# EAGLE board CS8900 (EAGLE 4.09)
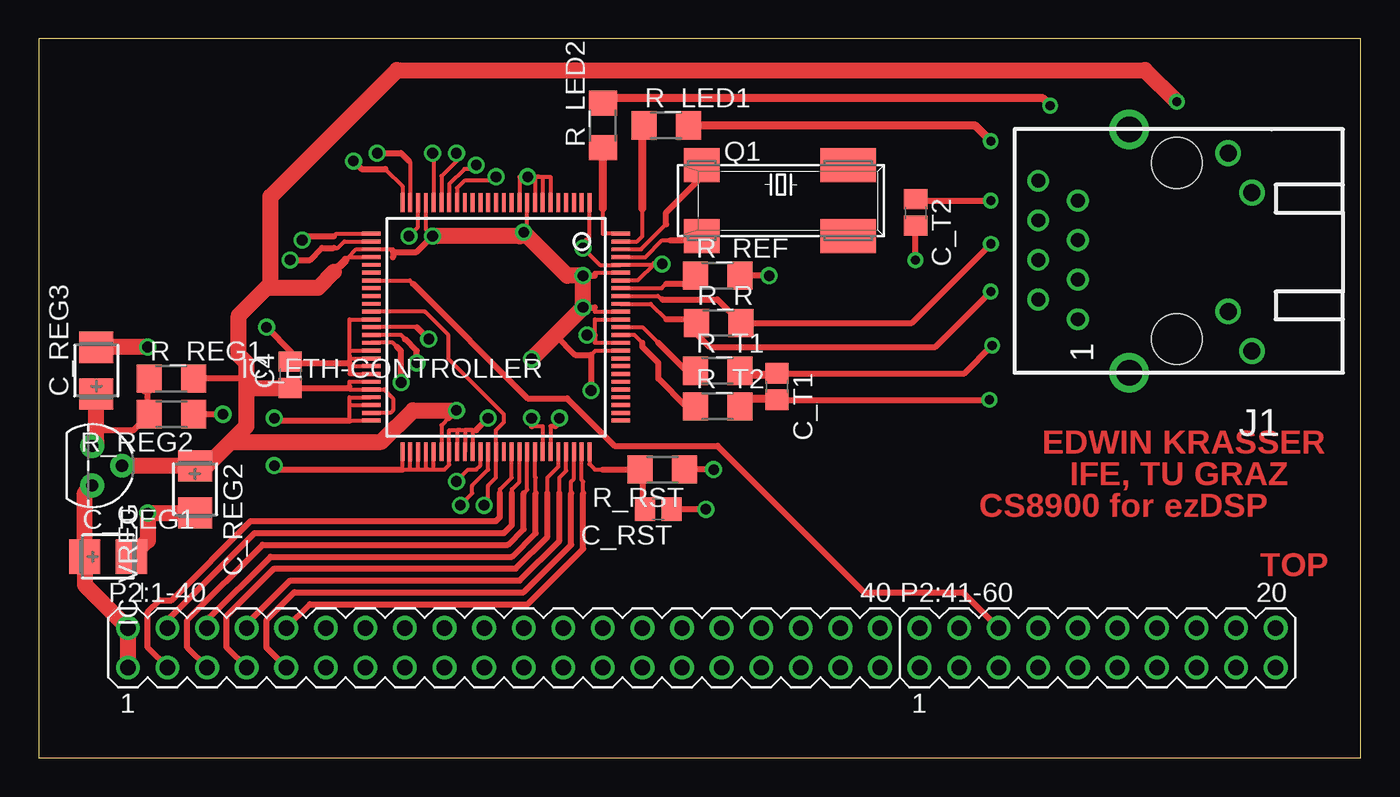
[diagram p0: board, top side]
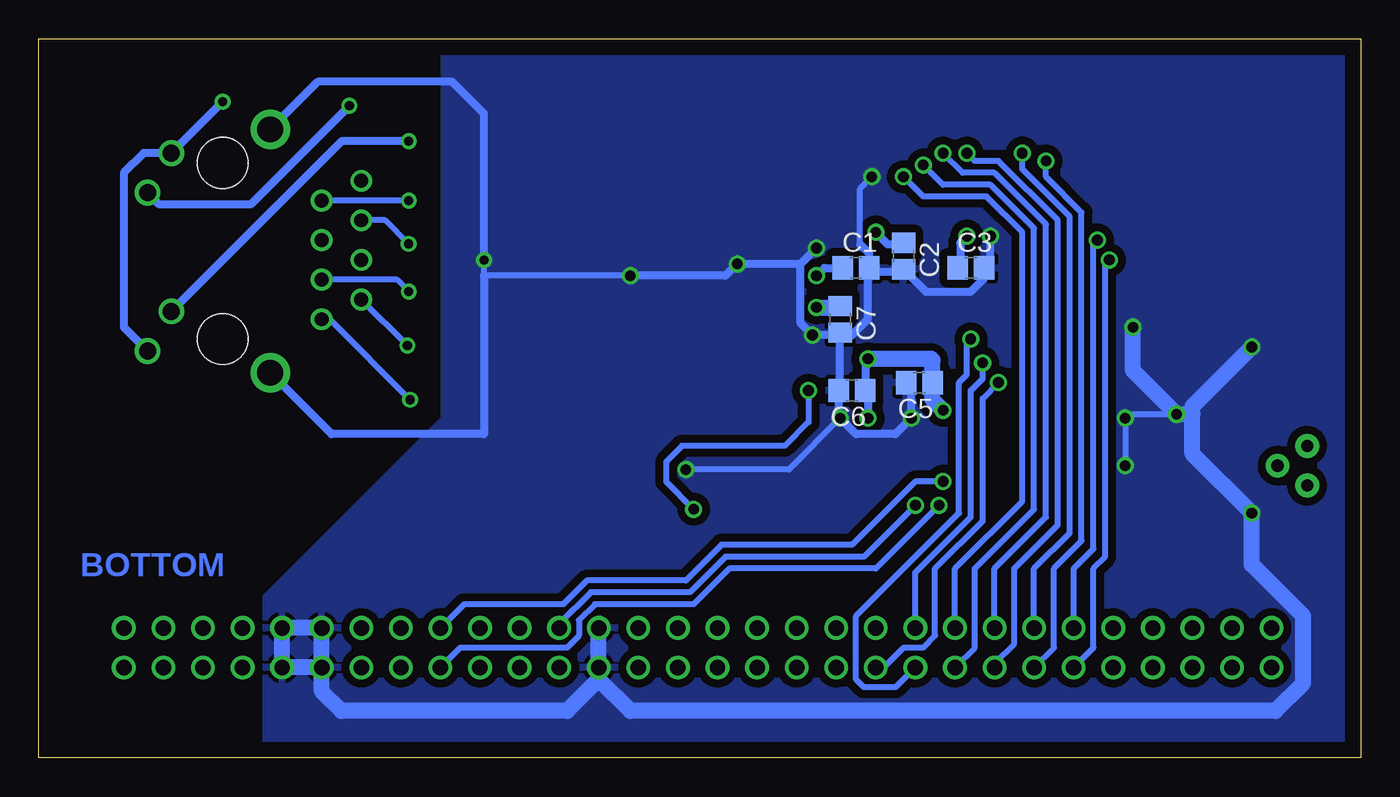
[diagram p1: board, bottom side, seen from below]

Size 84.82 x 46.15 mm. Coordinates in mm from the lower left corner, seen from the top.
Outline: 0,0 84.82,0 84.82,46.15 0,46.15 0,0
Copper layers used: Top, Bottom

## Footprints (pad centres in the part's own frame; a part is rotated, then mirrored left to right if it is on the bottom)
C0805 = smd 1.3 x 1.5: 1 -0.85,0; 2 0.85,0
CT3528 = smd 2 x 2.2: + -1.5,0; - 1.5,0
100L_TQFP = smd 0.25 x 1.2: P$1 -6,-8; P$2 -5.5,-8; P$3 -5,-8; P$4 -4.5,-8; P$5 -4,-8; P$6 -3.5,-8; P$7 -3,-8; P$8 -2.5,-8; P$9 -2,-8; P$10 -1.5,-8; P$11 -1,-8; P$12 -0.5,-8; P$13 0,-8; P$14 0.5,-8; P$15 1,-8; P$16 1.5,-8; P$17 2,-8; P$18 2.5,-8; P$19 3,-8; P$20 3.5,-8; P$21 4,-8; P$22 4.5,-8; P$23 5,-8; P$24 5.5,-8; P$25 6,-8; P$51 6,8; P$52 5.5,8; P$53 5,8; P$54 4.5,8; P$55 4,8; P$56 3.5,8; P$57 3,8; P$58 2.5,8; P$59 2,8; P$60 1.5,8; P$61 1,8; P$62 0.5,8; P$63 0,8; P$64 -0.5,8; P$65 -1,8; P$66 -1.5,8; P$67 -2,8; P$68 -2.5,8; P$69 -3,8; P$70 -3.5,8; P$71 -4,8; P$72 -4.5,8; P$73 -5,8; P$74 -5.5,8; P$75 -6,8 | smd 1.2 x 0.25: P$26 8,-6; P$27 8,-5.5; P$28 8,-5; P$29 8,-4.5; P$30 8,-4; P$31 8,-3.5; P$32 8,-3; P$33 8,-2.5; P$34 8,-2; P$35 8,-1.5; P$36 8,-1; P$37 8,-0.5; P$38 8,0; P$39 8,0.5; P$40 8,1; P$41 8,1.5; P$42 8,2; P$43 8,2.5; P$44 8,3; P$45 8,3.5; P$46 8,4; P$47 8,4.5; P$48 8,5; P$49 8,5.5; P$50 8,6; P$76 -8,6; P$77 -8,5.5; P$78 -8,5; P$79 -8,4.5; P$80 -8,4; P$81 -8,3.5; P$82 -8,3; P$83 -8,2.5; P$84 -8,2; P$85 -8,1.5; P$86 -8,1; P$87 -8,0.5; P$88 -8,0; P$89 -8,-0.5; P$90 -8,-1; P$91 -8,-1.5; P$92 -8,-2; P$93 -8,-2.5; P$94 -8,-3; P$95 -8,-3.5; P$96 -8,-4; P$97 -8,-4.5; P$98 -8,-5; P$99 -8,-5.5; P$100 -8,-6
TO92 = drill 0.787 pad 1.524 round: 1 -1.27,0; 2 0,1.905; 3 1.27,0
STARJACK = drill 0.889 round: 1 4.318,-7.62; 2 3.048,-10.16; 3 1.778,-7.62; 4 0.508,-10.16; 5 -0.762,-7.62; 6 -2.032,-10.16; 7 -3.302,-7.62; 8 -4.572,-10.16 | drill 1.092 pad 1.651 round: 9 6.35,3.556; 10 3.81,2.032; 11 -3.81,3.556; 12 -6.35,2.032 | drill 1.651 pad 2.54 round: G1 7.747,-4.318; G2 -7.874,-4.318 | hole 3.251: 5.588,-1.27; -5.715,-1.27
MA20-2 = drill 0.991 pad 1.524 round: 1 -24.13,-1.27; 2 -24.13,1.27; 3 -21.59,-1.27; 4 -21.59,1.27; 5 -19.05,-1.27; 6 -19.05,1.27; 7 -16.51,-1.27; 8 -16.51,1.27; 9 -13.97,-1.27; 10 -13.97,1.27; 11 -11.43,-1.27; 12 -11.43,1.27; 13 -8.89,-1.27; 14 -8.89,1.27; 15 -6.35,-1.27; 16 -6.35,1.27; 17 -3.81,-1.27; 18 -3.81,1.27; 19 -1.27,-1.27; 20 -1.27,1.27; 21 1.27,-1.27; 22 1.27,1.27; 23 3.81,-1.27; 24 3.81,1.27; 25 6.35,-1.27; 26 6.35,1.27; 27 8.89,-1.27; 28 8.89,1.27; 29 11.43,-1.27; 30 11.43,1.27; 31 13.97,-1.27; 32 13.97,1.27; 33 16.51,-1.27; 34 16.51,1.27; 35 19.05,-1.27; 36 19.05,1.27; 37 21.59,-1.27; 38 21.59,1.27; 39 24.13,-1.27; 40 24.13,1.27
MA10-2 = drill 0.991 pad 1.524 round: 1 -11.43,-1.27; 2 -11.43,1.27; 3 -8.89,-1.27; 4 -8.89,1.27; 5 -6.35,-1.27; 6 -6.35,1.27; 7 -3.81,-1.27; 8 -3.81,1.27; 9 -1.27,-1.27; 10 -1.27,1.27; 11 1.27,-1.27; 12 1.27,1.27; 13 3.81,-1.27; 14 3.81,1.27; 15 6.35,-1.27; 16 6.35,1.27; 17 8.89,-1.27; 18 8.89,1.27; 19 11.43,-1.27; 20 11.43,1.27
86SMX = smd 2.286 x 2.184: 1 -5.08,-2.286; 4 -5.08,2.286 | smd 3.556 x 2.184: 2 4.318,-2.286; 3 4.318,2.286
R1206 = smd 1.6 x 1.803: 1 -1.422,0; 2 1.422,0

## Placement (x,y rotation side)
C1  100n  [C0805]  32.38,31.46 0 bottom
C2  100n  [C0805]  29.33,32.22 270 bottom
C3  100n  [C0805]  25.01,31.46 0 bottom
C4  100n  [C0805]  16.12,24.6 90 top
C5  100n  [C0805]  28.32,24.09 180 bottom
C6  100n  [C0805]  32.63,23.58 180 bottom
C7  100n  [C0805]  33.4,28.16 270 bottom
C_REG1  10u  [CT3528]  4.44,12.92 0 top
C_REG2  10u  [CT3528]  10.03,17.23 270 top
C_REG3  10u  [CT3528]  3.68,24.85 90 top
C_RST  100n  [C0805]  39.75,15.96 180 top
C_T1  560p  [C0805]  47.37,23.84 270 top
C_T2  100n  [C0805]  56.26,35.01 270 top
IC_ETH-CONTROLLER  CS8900A-CQ3  [100L_TQFP]  29.33,27.65 180 top
IC_VREG  LM317LZ  [TO92]  3.42,18.76 270 top
J1  STARJACK_J00-0051  [STARJACK]  74.29,32.47 270 top
P2:1-40  [MA20-2]  29.84,7.07 0 top
P2:41-60  [MA10-2]  67.94,7.07 0 top
Q1  20MHz  [86SMX]  47.62,35.78 0 top
R_LED1  510  [R1206]  40.25,40.6 0 top
R_LED2  510  [R1206]  36.19,40.6 90 top
R_R  100  [R1206]  43.63,27.92 0 top
R_REF  4.99k  [R1206]  43.56,30.95 0 top
R_REG1  620  [R1206]  8.5,24.35 0 top
R_REG2  1k  [R1206]  8.5,22.06 180 top
R_RST  10k  [R1206]  40,18.5 180 top
R_T1  8.2  [R1206]  43.56,24.85 0 top
R_T2  8.2  [R1206]  43.56,22.57 0 top

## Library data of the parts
C1-C7 C_REG1-C_REG3 C_RST C_T1 C_T2 R_LED1 R_LED2 R_R R_REF R_REG1 R_REG2 R_RST R_T1 R_T2 = rcl
IC_ETH-CONTROLLER = EthernetController
IC_VREG = linear
J1 = HARY_CON
P2:1-40 P2:41-60 = con-lstb
Q1 = crystal

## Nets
A0: IC_ETH-CONTROLLER.P$38 P2:1-40.19
A1: IC_ETH-CONTROLLER.P$39 P2:1-40.20
A2: IC_ETH-CONTROLLER.P$40 P2:1-40.21
GND: C1.2 C2.2 C3.2 C4.2 C5.2 C6.2 C7.2 C_REG1.- C_REG2.- C_REG3.- C_T2.2 IC_ETH-CONTROLLER.P$1 IC_ETH-CONTROLLER.P$6 IC_ETH-CONTROLLER.P$7 IC_ETH-CONTROLLER.P$8 IC_ETH-CONTROLLER.P$10 IC_ETH-CONTROLLER.P$23 IC_ETH-CONTROLLER.P$37 IC_ETH-CONTROLLER.P$41 IC_ETH-CONTROLLER.P$42 IC_ETH-CONTROLLER.P$43 IC_ETH-CONTROLLER.P$44 IC_ETH-CONTROLLER.P$47 IC_ETH-CONTROLLER.P$48 IC_ETH-CONTROLLER.P$50 IC_ETH-CONTROLLER.P$51 IC_ETH-CONTROLLER.P$52 IC_ETH-CONTROLLER.P$53 IC_ETH-CONTROLLER.P$54 IC_ETH-CONTROLLER.P$55 IC_ETH-CONTROLLER.P$57 IC_ETH-CONTROLLER.P$58 IC_ETH-CONTROLLER.P$59 IC_ETH-CONTROLLER.P$60 IC_ETH-CONTROLLER.P$70 IC_ETH-CONTROLLER.P$86 IC_ETH-CONTROLLER.P$89 IC_ETH-CONTROLLER.P$94 IC_ETH-CONTROLLER.P$96 J1.G1 J1.G2 P2:1-40.35 P2:1-40.36 P2:41-60.9 P2:41-60.10 P2:41-60.11 P2:41-60.12 R_REF.2 R_REG2.1 R_RST.1
INTRQ: IC_ETH-CONTROLLER.P$32 P2:41-60.6
N$1: IC_ETH-CONTROLLER.P$98 Q1.4
N$2: IC_ETH-CONTROLLER.P$88 R_T1.1
N$3: IC_ETH-CONTROLLER.P$93 R_REF.1
N$4: IC_ETH-CONTROLLER.P$87 R_T2.1
N$5: IC_ETH-CONTROLLER.P$99 R_LED1.1
N$6: IC_ETH-CONTROLLER.P$100 R_LED2.1
N$7: J1.10 R_LED1.2
N$8: J1.11 R_LED2.2
N$9: IC_ETH-CONTROLLER.P$97 Q1.1
N$10: C_REG3.+ IC_VREG.1 R_REG1.1 R_REG2.2
N$15: C_T2.1 J1.7
NCS: IC_ETH-CONTROLLER.P$36 IC_ETH-CONTROLLER.P$63 P2:1-40.38
NR: IC_ETH-CONTROLLER.P$61 P2:41-60.4
NW: IC_ETH-CONTROLLER.P$62 P2:41-60.3
RESET: C_RST.2 IC_ETH-CONTROLLER.P$75 R_RST.2
RXD+: IC_ETH-CONTROLLER.P$91 J1.3 R_R.1
RXD-: IC_ETH-CONTROLLER.P$92 J1.6 R_R.2
SD0: IC_ETH-CONTROLLER.P$65 P2:1-40.3
SD1: IC_ETH-CONTROLLER.P$66 P2:1-40.4
SD2: IC_ETH-CONTROLLER.P$67 P2:1-40.5
SD3: IC_ETH-CONTROLLER.P$68 P2:1-40.6
SD4: IC_ETH-CONTROLLER.P$71 P2:1-40.7
SD5: IC_ETH-CONTROLLER.P$72 P2:1-40.8
SD6: IC_ETH-CONTROLLER.P$73 P2:1-40.9
SD7: IC_ETH-CONTROLLER.P$74 P2:1-40.10
SD8: IC_ETH-CONTROLLER.P$27 P2:1-40.11
SD9: IC_ETH-CONTROLLER.P$26 P2:1-40.12
SD10: IC_ETH-CONTROLLER.P$25 P2:1-40.13
SD11: IC_ETH-CONTROLLER.P$24 P2:1-40.14
SD12: IC_ETH-CONTROLLER.P$21 P2:1-40.15
SD13: IC_ETH-CONTROLLER.P$20 P2:1-40.16
SD14: IC_ETH-CONTROLLER.P$19 P2:1-40.17
SD15: IC_ETH-CONTROLLER.P$18 P2:1-40.18
TXD+: C_T1.1 J1.2 R_T1.2
TXD-: C_T1.2 J1.1 R_T2.2
V3.3: C1.1 C2.1 C3.1 C4.1 C5.1 C6.1 C7.1 C_REG2.+ C_RST.1 IC_ETH-CONTROLLER.P$9 IC_ETH-CONTROLLER.P$22 IC_ETH-CONTROLLER.P$28 IC_ETH-CONTROLLER.P$29 IC_ETH-CONTROLLER.P$45 IC_ETH-CONTROLLER.P$46 IC_ETH-CONTROLLER.P$49 IC_ETH-CONTROLLER.P$56 IC_ETH-CONTROLLER.P$69 IC_ETH-CONTROLLER.P$85 IC_ETH-CONTROLLER.P$90 IC_ETH-CONTROLLER.P$95 IC_VREG.2 J1.9 J1.12 R_REG1.2
V5: C_REG1.+ IC_VREG.3 P2:1-40.1 P2:1-40.2

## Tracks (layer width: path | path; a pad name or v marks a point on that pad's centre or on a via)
A0  (via drill 0.69 pad 1.02)
  Top 0.254: 24.25,27.65 IC_ETH-CONTROLLER.P$38
  Top 0.381: v25.01,26.89 24.25,27.65
  Bottom 0.381: P2:1-40.19 29.84,4.53 31.87,4.53 32.38,5.04 32.38,9.11 25.78,15.71 25.78,24.09 25.27,24.6 25.27,26.63 v25.01,26.89
A1  (via drill 0.69 pad 1.02)
  Top 0.254: IC_ETH-CONTROLLER.P$39 23.23,27.15 23.49,26.89
  Top 0.381: 23.49,26.89 24.25,26.12 v24.25,25.36
  Bottom 0.381: P2:1-40.20 28.57,11.9 25.01,15.46 25.01,23.58 24.25,24.35 v24.25,25.36
A2  (via drill 0.69 pad 1.02)
  Top 0.254: IC_ETH-CONTROLLER.P$40 22.71,26.65 22.98,26.38
  Top 0.381: 22.98,26.38 23.24,26.12 v23.24,24.09
  Bottom 0.381: P2:1-40.21 30.6,5.8 29.33,7.07 28.06,7.07 27.3,7.84 27.3,12.15 24.25,15.2 24.25,23.08 v23.24,24.09
GND  (via drill 0.58 pad 1.02, 0.69 pad 1.02)
  Top 0.254: IC_ETH-CONTROLLER.P$86 35.68,26.65 35.68,27.14 35.68,28.15 IC_ETH-CONTROLLER.P$89 | IC_ETH-CONTROLLER.P$41 19.93,26.15 19.93,26.12 | 19.93,25.87 19.93,26.12 | 19.93,25.36 19.93,25.87 | IC_ETH-CONTROLLER.P$47 19.93,23.15 19.93,22.57 | IC_ETH-CONTROLLER.P$48 19.93,22.65 19.93,22.57 | IC_ETH-CONTROLLER.P$51 23.33,18.5 23.74,18.5 | IC_ETH-CONTROLLER.P$52 23.83,18.5 23.74,18.5 | IC_ETH-CONTROLLER.P$53 24.33,18.5 23.74,18.5 | IC_ETH-CONTROLLER.P$54 24.83,18.5 25.01,18.5 | IC_ETH-CONTROLLER.P$55 25.33,18.5 25.27,18.5 | 25.01,18.5 25.27,18.5 | 23.74,18.5 25.01,18.5 | 27.83,21.04 IC_ETH-CONTROLLER.P$60 | 27.83,21.04 28.06,21.04 | 27.33,21.04 IC_ETH-CONTROLLER.P$59 | 27.05,21.04 27.83,21.04 | IC_ETH-CONTROLLER.P$58 26.83,21.04 27.05,21.04 | 27.05,21.04 26.33,21.04 IC_ETH-CONTROLLER.P$57 26.33,18.81 26.03,18.5 25.27,18.5 | 27.33,21.04 27.3,21.04 | 27.83,21.04 27.33,21.04 | IC_ETH-CONTROLLER.P$1 35.33,33.39 35.17,33.24 | IC_ETH-CONTROLLER.P$23 24.33,34.08 v23.74,33.49 | IC_ETH-CONTROLLER.P$70 32.83,21.3 33.14,21.3 | IC_ETH-CONTROLLER.P$37 19.93,28.15 19.93,26.12 | IC_ETH-CONTROLLER.P$42 19.93,25.65 19.93,25.87 | IC_ETH-CONTROLLER.P$43 19.93,25.15 19.93,25.36 | IC_ETH-CONTROLLER.P$44 19.93,24.65 19.93,25.36 | IC_ETH-CONTROLLER.P$50 19.93,21.65 19.93,22.57 | IC_ETH-CONTROLLER.P$10 30.83,37.3 v31.36,37.3 31.83,37.3 | 31.83,37.3 IC_ETH-CONTROLLER.P$8 | v34.92,32.73 36,31.65 IC_ETH-CONTROLLER.P$96 39.49,31.65 39.49,31.71 38.43,30.65 IC_ETH-CONTROLLER.P$94 | IC_ETH-CONTROLLER.P$7 32.33,37.3 32.13,37.3 | 32.13,37.3 31.87,37.3 | 31.83,37.3 32.13,37.3 | IC_ETH-CONTROLLER.P$6 32.83,37.3 32.13,37.3
  Top 0.381: v11.81,22.06 R_REG2.1 | 28.06,21.04 v28.82,21.81 | v35.17,27.14 35.68,27.14 | 16.21,25.36 C4.2 | 16.21,25.36 16.21,26.04 v14.6,27.65 | v33.4,21.81 33.4,21.55 33.14,21.3 | 16.21,25.36 19.93,25.36 | 19.93,21.65 15.27,21.65 v15.11,21.81 | 23.33,18.5 15.36,18.5 v15.11,18.76 | v43.3,18.5 R_RST.1 | v46.86,30.95 R_REF.2 | v40,31.71 39.49,31.71 | 35.17,33.24 34.92,32.98 v34.92,32.73 | v56.26,31.97 C_T2.2
  Top 1.016: C_REG3.- 3.7,26.38 v6.98,26.38 | C_REG2.- 10,15.71 v6.98,15.71 6.98,13.96 C_REG1.-
  Bottom 0.381: 28.82,23.58 C5.2 | C6.2 33.4,23.67 | C7.2 33.56,27.14 32.89,27.14 32.63,27.14 | 31.28,31.2 C1.2 31.62,31.37 | 29.5,31.2 C2.2 | 23.74,31.88 C3.2 24.16,30.78 | v11.81,22.06 14.85,22.06 v15.11,21.81 v15.11,18.76 | v43.3,18.5 36.7,18.5 v33.4,21.81 | v31.36,37.3 32.13,36.54 32.13,32.98 | v56.26,31.97 56.26,30.95 v46.86,30.95
  Bottom 0.508: 28.82,23.58 v28.82,21.81 29.84,20.79 32.38,20.79 v33.4,21.81 33.48,21.89 C6.2 | 33.4,23.67 C7.2 | 31.28,31.2 29.5,31.2 | 32.63,27.14 31.62,28.16 31.62,31.37 | 32.89,27.14 v35.17,27.14 35.94,27.9 35.94,31.71 | 23.74,31.88 v23.74,33.49 | 24.16,30.78 25.01,29.93 27.9,29.93 C2.2 | 35.94,31.71 v40,31.71 40.76,30.95 v46.86,30.95 | 35.94,31.71 v34.92,32.73 | C1.2 31.53,32.39 32.13,32.98 | J1.G2 66.92,43.4 58.29,43.4 56.26,41.36 56.26,32.22 | J1.G1 66.03,20.79 56.26,20.79 56.26,30.95
  Bottom 1.016: v6.98,26.38 10.79,22.57 10.79,22.06 | 10.79,22.06 v11.81,22.06 14.6,24.85 v14.6,27.65 | 10.79,22.06 10.79,19.52 v6.98,15.71 6.98,12.41 3.68,9.11 3.68,4.79 5.46,3.01 46.86,3.01 48.89,5.04 | P2:41-60.12 P2:41-60.10 P2:41-60.9 | 69.21,6.06 69.46,5.8 P2:41-60.11 | 69.21,6.06 69.21,8.6 | P2:41-60.9 66.67,4.28 65.4,3.01 50.92,3.01 48.89,5.04 | P2:1-40.36 P2:1-40.35 48.89,5.04 | P2:41-60.9 P2:41-60.11 | P2:41-60.11 69.21,6.06
  pour Bottom (isolate 0.508): 0.63,45.17 0.63,0.98 70.23,0.98 70.23,10.38 58.8,21.81 58.8,45.17 22.47,45.17
INTRQ
  Top 0.254: IC_ETH-CONTROLLER.P$32 23.79,30.65 24,30.44
  Top 0.381: 24,30.44 31.36,23.08 33.9,23.08 36.95,20.03 43.56,20.03 52.95,10.63 59.3,10.63 P2:41-60.6
N$1
  Top 0.254: IC_ETH-CONTROLLER.P$98 38.65,32.65 40.25,34.25
  Top 0.305: 42.54,37.3 Q1.4
  Top 0.381: 42.54,37.3 40.25,35.01 40.25,34.25
N$2
  Top 0.254: IC_ETH-CONTROLLER.P$88 38.73,27.65 39.75,26.63
  Top 0.381: R_T1.1 41.52,24.85 39.75,26.63
N$3
  Top 0.254: IC_ETH-CONTROLLER.P$93 39.96,30.15 40.25,30.44
  Top 0.381: R_REF.1 41.63,30.44 40.25,30.44
N$4
  Top 0.254: IC_ETH-CONTROLLER.P$87 38.21,27.15 38.73,26.63
  Top 0.381: R_T2.1 41.52,22.57 39.75,24.35 39.75,25.36 38.73,26.38 38.73,26.63
N$5
  Top 0.254: IC_ETH-CONTROLLER.P$99 38.39,33.15 38.73,33.49 38.73,35.27
  Top 0.508: R_LED1.1 38.73,40.5 38.73,35.27
N$6
  Top 0.254: IC_ETH-CONTROLLER.P$100 36.19,33.65 36.19,35.27
  Top 0.508: 36.19,35.27 R_LED2.1
N$7  (via drill 0.58 pad 1.02)
  Top 0.508: R_LED1.2 60.07,40.6 v61.08,39.59
  Bottom 0.508: J1.10 65.4,39.59 v61.08,39.59
N$8  (via drill 0.58 pad 1.02)
  Top 0.508: v64.89,41.87 64.38,42.38 36.55,42.38 R_LED2.2
  Bottom 0.508: v64.89,41.87 71.24,35.52 77.08,35.52 J1.11
N$9
  Top 0.254: IC_ETH-CONTROLLER.P$97 38.91,32.15 40,33.24 40.51,33.24
  Top 0.305: 42.29,33.24 Q1.1
  Top 0.381: 40.51,33.24 42.29,33.24
N$10
  Top 0.381: IC_VREG.1 3.42,20.79 3.68,21.04 6.07,21.04 R_REG2.2 6.98,21.91 6.98,23.75 6.89,23.84
  Top 1.016: 3.34,20.12 IC_VREG.1 3.68,20.28 3.68,21.04 C_REG3.+ 4.16,23.84 | 6.89,23.84 R_REG1.1
N$15  (via drill 0.58 pad 1.02)
  Top 0.381: C_T2.1 56.34,35.78 v61.08,35.78
  Bottom 0.381: v61.08,35.78 J1.7
NCS  (via drill 0.69 pad 1.02)
  Top 0.254: v28.57,16.22 28.82,16.47 28.82,17.49 29.33,18 IC_ETH-CONTROLLER.P$63 29.33,21.04 29.84,21.55 29.84,22.06 26.28,25.62 26.28,27.14 24.78,28.65 IC_ETH-CONTROLLER.P$36
  Bottom 0.381: v28.57,16.22 31.87,12.92 40.76,12.92 43.05,10.63 49.4,10.63 51.43,8.6 P2:1-40.38
NR  (via drill 0.69 pad 1.02)
  Top 0.254: IC_ETH-CONTROLLER.P$61 28.33,18.77 28.06,18.5 27.55,18.5 v26.79,17.74
  Bottom 0.381: v26.79,17.74 28.57,17.74 32.63,13.68 41.02,13.68 43.3,11.39 49.65,11.39 51.18,9.87 57.53,9.87 P2:41-60.4
NW  (via drill 0.69 pad 1.02)
  Top 0.254: IC_ETH-CONTROLLER.P$62 28.83,18.51 27.81,17.49 27.81,16.98 v27.05,16.22
  Bottom 0.381: v27.05,16.22 31.11,12.15 40.51,12.15 42.79,9.87 49.14,9.87 50.16,8.85 50.16,7.84 50.92,7.07 57.78,7.07 P2:41-60.3
RESET
  Top 0.254: IC_ETH-CONTROLLER.P$75 35.33,18.85 35.68,18.5 36.19,18.5
  Top 0.381: 36.19,18.5 R_RST.2 38.58,18.4 38.73,18.25 38.73,16.13 C_RST.2
RXD+  (via drill 0.58 pad 1.02)
  Top 0.254: IC_ETH-CONTROLLER.P$91 39.26,29.15 40.25,28.16
  Top 0.381: 40.25,28.16 41.97,28.16 R_R.1 42.2,27.22 43.05,26.38 57.53,26.38 v61.08,29.93
  Bottom 0.381: v61.08,29.93 61.84,30.7 J1.3
RXD-  (via drill 0.58 pad 1.02)
  Top 0.254: IC_ETH-CONTROLLER.P$92 39.71,29.65 40,29.43
  Top 0.381: 40,29.43 43.54,29.43 R_R.2 56.02,27.92 v61.1,33
  Bottom 0.381: v61.1,33 62.61,34.51 J1.6
SD0
  Top 0.254: 29.59,16.98 29.59,17.23 30.33,17.98 IC_ETH-CONTROLLER.P$65
  Top 0.381: P2:1-40.3 6.98,7.07 6.98,9.36 7.74,10.12 8.5,10.12 13.58,15.2 29.33,15.2 29.59,15.46 29.59,16.98
SD1
  Top 0.254: 30.35,16.98 30.35,17.23 30.83,17.72 IC_ETH-CONTROLLER.P$66
  Top 0.381: P2:1-40.4 8.25,8.85 13.84,14.44 29.84,14.44 30.35,14.95 30.35,16.98
SD2
  Top 0.254: IC_ETH-CONTROLLER.P$67 31.33,17.2 31.11,16.98
  Top 0.381: P2:1-40.5 9.52,7.07 9.52,8.85 14.35,13.68 30.09,13.68 31.11,14.69 31.11,16.98
SD3
  Top 0.254: IC_ETH-CONTROLLER.P$68 31.83,18.04 31.87,18 31.87,16.98
  Top 0.381: P2:1-40.6 10.79,8.85 14.85,12.92 30.35,12.92 31.87,14.44 31.87,16.98
SD4
  Top 0.254: IC_ETH-CONTROLLER.P$71 33.33,18.69 32.63,18 32.63,16.98
  Top 0.381: P2:1-40.7 12.06,7.07 12.06,9.11 15.11,12.15 30.6,12.15 32.63,14.19 32.63,16.98
SD5
  Top 0.254: IC_ETH-CONTROLLER.P$72 33.83,18.43 33.4,18 33.4,16.98
  Top 0.381: P2:1-40.8 13.33,8.6 16.12,11.39 30.86,11.39 33.4,13.93 33.4,16.98
SD6
  Top 0.254: IC_ETH-CONTROLLER.P$73 34.33,17.92 34.16,17.74 34.16,16.98
  Top 0.381: P2:1-40.9 14.6,7.07 14.6,8.85 16.38,10.63 31.11,10.63 34.16,13.68 34.16,16.98
SD7
  Top 0.254: IC_ETH-CONTROLLER.P$74 34.83,17.83 34.92,17.74 34.92,16.98
  Top 0.381: P2:1-40.10 17.39,9.87 31.36,9.87 34.92,13.42 34.92,16.98
SD8  (via drill 0.69 pad 1.02)
  Top 0.254: 18.92,32.73 19.17,32.73 19.59,33.15 IC_ETH-CONTROLLER.P$27
  Top 0.381: v16.12,31.97 17.39,31.97 18.16,32.73 18.92,32.73
  Bottom 0.381: P2:1-40.11 17.14,7.07 17.14,12.15 16.38,12.92 16.38,31.71 v16.12,31.97
SD9  (via drill 0.69 pad 1.02)
  Top 0.254: IC_ETH-CONTROLLER.P$26 19.08,33.65 18.92,33.49
  Top 0.381: v16.89,33.24 17.14,33.49 18.92,33.49
  Bottom 0.381: P2:1-40.12 18.41,12.15 17.14,13.42 17.14,32.98 v16.89,33.24
SD10  (via drill 0.69 pad 1.02)
  Top 0.254: IC_ETH-CONTROLLER.P$25 23.33,36.7 22.22,37.81
  Top 0.381: v20.19,38.32 20.7,37.81 22.22,37.81
  Bottom 0.381: P2:1-40.13 19.68,7.07 19.68,12.15 17.9,13.93 17.9,35.01 20.19,37.3 v20.19,38.32
SD11  (via drill 0.69 pad 1.02)
  Top 0.254: IC_ETH-CONTROLLER.P$24 23.83,38.23 23.74,38.32
  Top 0.381: v21.71,38.82 23.24,38.82 23.74,38.32
  Bottom 0.381: P2:1-40.14 20.95,12.15 18.66,14.44 18.66,34.76 21.71,37.81 v21.71,38.82
SD12  (via drill 0.69 pad 1.02)
  Top 0.254: v25.27,38.82 25.27,38.57 25.33,38.51 IC_ETH-CONTROLLER.P$21
  Bottom 0.381: P2:1-40.15 23.49,6.06 22.22,7.33 22.22,12.15 19.43,14.95 19.43,34.51 23.24,38.32 24.76,38.32 v25.27,38.82
SD13  (via drill 0.69 pad 1.02)
  Top 0.254: IC_ETH-CONTROLLER.P$20 25.83,37.36 26.79,38.32 v26.79,38.82
  Bottom 0.381: P2:1-40.16 23.49,12.15 20.19,15.46 20.19,34.25 23.49,37.55 25.52,37.55 v26.79,38.82
SD14  (via drill 0.69 pad 1.02)
  Top 0.254: IC_ETH-CONTROLLER.P$19 26.33,36.84 27.3,37.81 27.81,37.81 v28.06,38.06
  Bottom 0.381: P2:1-40.17 24.76,7.07 24.76,12.15 20.95,15.96 20.95,34 23.74,36.79 26.79,36.79 v28.06,38.06
SD15  (via drill 0.69 pad 1.02)
  Top 0.254: IC_ETH-CONTROLLER.P$18 26.83,36.58 27.3,37.05 29.08,37.05 v29.33,37.3
  Bottom 0.381: P2:1-40.18 26.03,12.15 21.71,16.47 21.71,33.74 24,36.03 28.06,36.03 v29.33,37.3
TXD+  (via drill 0.58 pad 1.02)
  Top 0.381: C_T1.1 59.39,24.69 v61.17,26.47
  Top 0.508: C_T1.1 47.28,24.6 45.23,24.6 R_T1.2
  Bottom 0.381: v61.17,26.47 J1.2
TXD-  (via drill 0.58 pad 1.02)
  Top 0.381: C_T1.2 v60.99,22.99
  Top 0.508: R_T2.2 45.49,23.08 47.28,23.08 C_T1.2
  Bottom 0.381: J1.1 66.16,28.16 v60.99,22.99
V3.3  (via drill 0.58 pad 1.02, 0.69 pad 1.02)
  Top 0.254: IC_ETH-CONTROLLER.P$90 35.68,28.65 35.68,28.92 | IC_ETH-CONTROLLER.P$69 32.33,21.3 31.62,21.3 | IC_ETH-CONTROLLER.P$45 19.93,24.15 19.93,23.84 19.93,23.65 IC_ETH-CONTROLLER.P$46 22.16,23.65 22.73,23.08 22.73,22.31 22.56,22.15 IC_ETH-CONTROLLER.P$49 | IC_ETH-CONTROLLER.P$56 25.83,21.35 26.28,21.81 | IC_ETH-CONTROLLER.P$95 35.68,31.15 35.68,30.95 | IC_ETH-CONTROLLER.P$9 31.33,33.97 v31.11,33.74 | IC_ETH-CONTROLLER.P$85 35.71,26.15 35.43,25.87 | IC_ETH-CONTROLLER.P$22 24.83,33.93 v25.27,33.49 | 22.73,32.47 22.73,32.65 IC_ETH-CONTROLLER.P$28 20.36,32.65 19.86,32.15 | 19.86,32.15 IC_ETH-CONTROLLER.P$29 | 19.68,31.97 19.86,32.15
  Top 0.381: 13.33,24.35 R_REG1.2 | v31.62,21.81 31.62,21.3 | v26.79,22.31 26.28,21.81 | v34.92,30.95 35.68,30.95 | 33.14,27.14 34.41,25.87 35.43,25.87 v35.43,23.58 | 22.73,32.15 22.73,32.47 24.25,32.47 v25.27,33.49 | C4.1 19.85,23.75 19.93,23.84 | v34.92,28.92 35.68,28.92 | v42.79,15.96 C_RST.1
  Top 0.508: 18.92,31.2 19.68,31.97
  Top 1.016: 10,18.76 C_REG2.+ | IC_VREG.2 10,18.76 | 10,18.76 10.79,18.76 12.31,20.28 | 12.31,20.28 13.33,21.3 13.33,24.35 | v31.62,25.62 33.14,27.14 v34.92,28.92 v34.92,30.95 33.9,30.95 v31.11,33.74 30.86,33.49 v25.27,33.49 | C4.1 13.33,23.75 13.33,24.35 | v26.79,22.31 24,22.31 21.97,20.28 12.31,20.28 | 18.92,31.2 17.9,30.19 14.85,30.19 | 14.85,30.19 14.6,30.19 12.82,28.41 12.82,25.87 13.33,25.36 13.33,24.35 | 14.85,30.19 14.85,36.03 22.98,44.16 70.99,44.16 v73.02,42.13
  Bottom 0.381: C6.1 31.62,23.42 | 33.48,28.92 C7.1 | C1.1 33.65,31.46 33.48,31.46 | 29.42,32.98 C2.1 | v31.62,25.62 31.78,25.45 | 27.47,24.26 C5.1 | C3.1 25.78,31.55 25.69,31.8 25.78,31.71 | v42.79,15.96 44.57,17.74 44.57,19.01 43.56,20.03 36.95,20.03 35.43,21.55 v35.43,23.58
  Bottom 0.508: 31.62,23.42 v31.62,21.81 | v34.92,30.95 34.41,31.46 33.65,31.46 | 31.78,25.45 C6.1 | 25.69,31.8 25.69,33.07 v25.27,33.49 | 29.42,32.98 30.35,32.98 v31.11,33.74 | J1.9 79.37,27.65 79.37,37.55 78.1,38.82 J1.12 v73.02,42.13
  Bottom 1.016: v26.79,22.31 27.47,22.99 27.47,24.26 27.47,25.53 27.55,25.62 v31.62,25.62 | v34.92,28.92 33.48,28.92
V5
  Top 1.016: P2:1-40.2 P2:1-40.1 | P2:1-40.2 5.71,8.6 | P2:1-40.2 2.94,11.11 C_REG1.+ 2.94,17 IC_VREG.3

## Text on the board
Top: EDWIN KRASSER | IFE, TU GRAZ | CS8900 for ezDSP | TOP
Bottom: BOTTOM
